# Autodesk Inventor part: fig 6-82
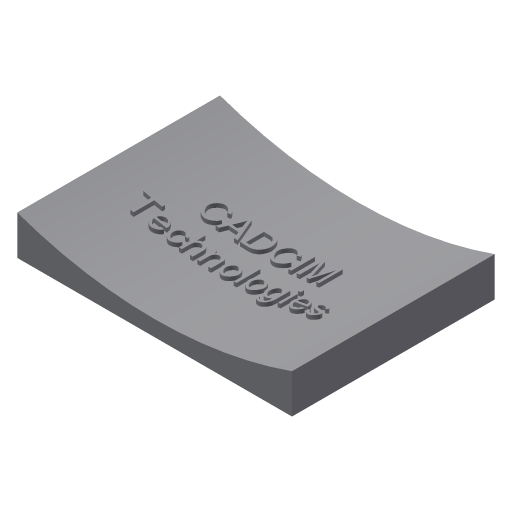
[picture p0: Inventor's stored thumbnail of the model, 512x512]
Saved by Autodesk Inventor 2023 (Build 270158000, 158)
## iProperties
Part Number: fig 6-82
Document SubType Name: Modeling
Created: 2002-12
Designer: deepak
Density: 1 g/cm^3
Material: Generic
Appearance: Default
Control State: 0
Master: False
Checked Out: False
Shininess: 64.0
Length Units: 11269
Angle Units: 11279
Time Units: 11290
Mass Units: 11283
Length Display Precision: 3
Angle Display Precision: 2
Compacted: True
Density: 0.0
Volumn: 0.0
Area: 0.0
PropertySet Name: Model Information
Author: deepak
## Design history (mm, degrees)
sketch "Sketch1"
  geometry: L1 (-39.922, 33.786)-(30.103, 33.786); L2 (30.103, 33.786)-(30.103, -17.894); L3 (30.103, -17.894)-(-39.922, -17.894); L4 (-39.922, -17.894)-(-39.922, 33.786)
  constraints: 8 end point, 2 parallel, 1 horizontal, 1 perpendicular
extrude "Extrusion1" new body sketch "Sketch1" distance "d0" = 10; taper "d1" = 0 deg
workplane "Work Plane1"
sketch "Sketch2"
  geometry: L1 (-37.656, 15.034)-(26.28, 15.034); L2 (26.28, 15.034)-(26.28, 10.168); L3 (26.28, 10.168)-(-37.656, 10.168); L4 (-37.656, 10.168)-(-37.656, 15.034)
  constraints: 2 other
sketch "Sketch3"
  geometry: L1 (70.026, 10)-(0, 10) reference; A1 r 105 centre (35.013, 108.99) between (0, 10) and (70.026, 10)
  constraints: 2 point on circle, 1 centre point
  dimensions: "d5" = 105 radius of A1
extrude "Extrusion2" cut sketch "Sketch3" extent not by distance; stored distance "d3" = 10; taper "d4" = 0 deg
emboss "Emboss4" sketch "Sketch2" dims "d14" = 1, "d15" = 0
body "Solid1"
other parameters: "d2" = 5
